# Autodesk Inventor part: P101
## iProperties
Author: Administrator
Revision Number: A
Shininess: 41.0
PropertySet Name: _Private Model Information
Created: 2000-11
Part Number: P101
Project: ACME
Description: PIN
Document SubType Name: Modeling
Designer: E. MOSS
Control State: 0
Master: False
Checked Out: False
PropertySet Name: Design Tracking Control
Density: 0.0
Volumn: 0.0
Area: 0.0
PropertySet Name: Model Information
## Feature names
1. Extrusion1
